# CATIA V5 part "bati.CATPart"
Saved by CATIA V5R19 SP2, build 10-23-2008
Part number: bâti
Publications: "Hcoulisseau", "L manivelle", "L bielle"
Bounding box of the stored display mesh (mm): x -30 to 30, y -65.728 to 320, z -200 to 30
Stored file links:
  C:\Users\pierre\Documents\IFMA\IAO\bati.CATPart
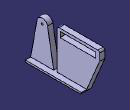
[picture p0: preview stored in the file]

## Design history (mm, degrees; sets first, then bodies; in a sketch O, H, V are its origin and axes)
Parameters
  Hcoulisseau = 30 mm
  `L manivelle` = 100 mm
  `L bielle` = 200 mm
Body1 (main body)
  Point1: (0, 0, 0)
  Sketch1 on yz-plane, origin (0, 0, 0), H (0, 1, 0), V (0, 0, 1)
    point P1 (29.5442, 5.2094)
    arc A1 centre (0, 0) radius 30 from (29.5442, 5.2094) to (-29.5442, 5.2094) ccw
    point P2 (0, 0)
    line L1 (-29.5442, 5.2094) -> (-65.7282, -200)
    line L2 (-65.7282, -200) -> (244.2718, -200)
    line L3 (320, 30) -> (83.9649, 30)
    line L4 (83.9649, 30) -> (83.9649, -190)
    line L5 (83.9649, -190) -> (63.9649, -190)
    line L6 (63.9649, -190) -> (29.5442, 5.2094)
    point P10 (29.5442, 5.2094)
    reference projected point E1 (0, 0) from Point1
    reference projected point E2 (0, 0) from Point1
    line L7 (320, 30) -> (320, -20)
    line L8 (320, -20) -> (244.2718, -200)
    reference projected point E3 (0, 0) from Point1
    angle L1 L2 = 80
    angle L6 L2 = 80
    radius A1 = 30
    distance L5 L2 = 10
    distance E2 L2 = 200 {= `L manivelle` +100mm}
    distance L3 L2 = 230
    length L5 = 20
    distance L7 E3 = 320 {= `L manivelle` +`L bielle` +20mm}
    length L7 = 50 {= Hcoulisseau +20mm}
    angle L7 L8 = 22.8171
    vertical: L4 V, L7 V
    coincidence: P10 P1, E1 P2
    tangency: L6 A1, A1 L1
    horizontal: L5 H, L2 H, L3 H
  Point2: (0, 100 {= `L manivelle`}, 0)
  Point3: (0, 300 {= `L manivelle` +`L bielle`}, 0)
  Plane1: type OffsetPt, RefPlane zx-plane, RefPoint Point2
  Plane2: type OffsetPt, RefPlane zx-plane, RefPoint Point3
  Line1: type PtPt, FirstPoint Point2, SecondPoint Point3
  Pad1: profile Sketch1, direction (1, 0, 0), length 30, mirrored extent
  Sketch2 on Plane1, origin (0, 100, 0), H (-1, 0, 0), V (0, 0, 1)
    line L1 (0, 30) -> (-30, 30)
    line L2 (-30, 30) -> (-30, -190)
    line L3 (-30, -190) -> (0, -190)
    line L4 (0, -190) -> (0, 30)
    reference projected point E1 (0, 0) from Point1
    reference projected line E2 (30, 30) -> (-30, 30) from edge [face of Pad1 from Sketch1.L3 | face of Pad1 from Sketch1.L7]
    reference projected line E3 (-30, -200) -> (-30, -20) from edge [face of Pad1 from Sketch1.L8 | end face of Pad1]
    reference projected point E4 (-30, -190) from edge [face of Pad1 from Sketch1.L5 | end face of Pad1]
    horizontal: L1 H, L3 H
    vertical: L2 V, L4 V
    coincidence: L4 E1, L1 E2, E3 L2, L3 E4
  Pocket1: profile Sketch2, direction (0, -1, 0), through (limit type 3), opposite side through (limit type 6)
  Sketch3 on face of Pocket1 from Sketch2.L4, origin (0, 0, 0), H (0, 1, 0), V (0, 0, 1)
    point P1 (0, 0)
    reference projected point E1 (0, 0) from Point1
    coincidence: E1 P1
  Hole1: placed by Sketch3, at (0, 0, 0) direction (-1, 0, 0), diameter 10, through (limit type 6)
  Sketch4 on face of Pocket1 from Sketch2.L4, origin (0, 0, 0), H (0, 1, 0), V (0, 0, 1)
    line L1 (100, 15) -> (300, 15)
    line L2 (300, 15) -> (300, -15)
    line L3 (300, -15) -> (100, -15)
    line L4 (100, -15) -> (100, 15)
    reference projected line E1 (100, 0) -> (300, 0) from Line1
    reference intersected line E2 through (100, 0) direction (0, 1) from Plane1
    reference intersected line E3 through (300, 0) direction (0, 1) from Plane2
    length L2 = 30 {= Hcoulisseau}
    horizontal: L1 H, L3 H
    vertical: L2 V, L4 V
    symmetry: L1 L3 E1
    coincidence: L4 E2, E3 L2
  Pocket2: profile Sketch4, direction (-1, 0, 0), through (limit type 6)
  Fillet1: radius 10, on edge [face of Pad1 from Sketch1.L3 | face of Pad1 from Sketch1.L7]; edge [face of Pad1 from Sketch1.L4 | face of Pad1 from Sketch1.L3]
